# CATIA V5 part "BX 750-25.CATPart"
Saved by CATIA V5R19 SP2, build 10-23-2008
Part number: BX 750-25
Bounding box of the stored display mesh (mm): x -47.487 to 47.487, y -47.487 to 47.487, z 0 to 145
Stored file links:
  C:\Users\Bora\Desktop\3D Katı model\BX serisi\BX 750\BX 750-25.CATPart
  C:\Program Files\Dassault Systemes\B19\intel_a\reffiles\standard\MetricThickPitch.txt
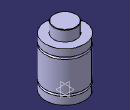
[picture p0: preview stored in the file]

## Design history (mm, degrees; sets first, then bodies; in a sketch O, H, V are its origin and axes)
Body1 (main body)
  Sketch1 on yz-plane, origin (0, 0, 0), H (0, 1, 0), V (0, 0, 1)
    point P1 (47.5, 101.5)
    point P2 (47.5, 96.5)
    point P3 (47.5, 23.5)
    point P4 (47.5, 18.5)
    point P6 (47.5, 101.5)
    point P7 (27.5, 144)
    point P9 (27.5, 144)
    point P11 (47.5, 96.5)
    point P12 (47.5, 23.5)
    point P13 (47.5, 18.5)
    arc A1 centre (47.5, 99) radius 2.5 from (47.5, 101.5) to (47.5, 96.5) ccw
    arc A2 centre (47.5, 21) radius 2.5 from (47.5, 23.5) to (47.5, 18.5) ccw
    line L1 (47.5, 119) -> (47.5, 101.5)
    line L2 (27.5, 144) -> (27.5, 119)
    arc A3 centre (26.5, 144) radius 1 from (27.5, 144) to (26.5, 145) ccw
    line L3 (47.5, 96.5) -> (47.5, 23.5)
    line L4 (47.5, 18.5) -> (47.5, 0)
    line L5 (26.5, 145) -> (0, 145)
    point P15 (0, 145)
    line L6 (27.5, 119) -> (47.5, 119)
    line L7 (47.5, 0) -> (0, 0)
    tangency: L5 A3
    coincidence: P15 V, P1 P6, P2 P11, P3 P12, P4 P13, P7 P9
    horizontal: L6 H, L7 H
  Shaft1: profile Sketch1, axis Sketch1.V, angle 360
  Sketch2 on face of Shaft1 from Sketch1.L7, origin (0, 0, 0), H (1, 0, 0), V (0, -1, 0)
    point P1 (25, 0)
    distance P1 V = 25
  Hole1: placed by Sketch2, at (25, 0, 0) direction (0, 0, 1), diameter 6.647, depth 10, threaded "M8", thread diameter 8, thread depth 10, pitch 1.25
  CircPattern1: of Hole1, instances 4, angular step 90, axis from xy-plane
